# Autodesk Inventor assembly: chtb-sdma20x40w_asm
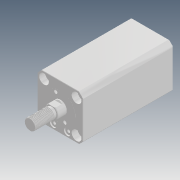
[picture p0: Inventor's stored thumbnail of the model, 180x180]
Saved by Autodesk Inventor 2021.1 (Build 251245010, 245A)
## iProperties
Company: Microsoft
Created: 2018-05
Part Number: chtb-sdma20x40w_asm
Description: STEP AP214
Document SubType Name: Assembly
Designer: user
Title: chtb-sdma20x40w_asm.STEP
Author: Windows
Revision Number: ÈÎºÎ
Sending System: SolidWorks 2015
Preprocessor: SwSTEP 2.0
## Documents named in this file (4)
- D:\Vault_2016\Projekty\Clamptek\Hydraulic\CHTB\CHTB-20\Inventor\CHTB-SDMA20x40W\chtb-sdma20x40w_asm.iam
- D:\Vault_2016\Projekty\Clamptek\Hydraulic\CHTB\CHTB-20\Inventor\CHTB-SDMA20x40W\CHTB-SDMA20X40NBT.ipt
- D:\Vault_2016\Projekty\Clamptek\Hydraulic\CHTB\CHTB-20\Inventor\CHTB-SDMA20x40W\CHTB-SDMA20X40WHSG.ipt
- D:\Vault_2016\Projekty\Clamptek\Hydraulic\CHTB\CHTB-20\Inventor\CHTB-SDMA20x40W\QG_3.ipt
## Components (3 placed, 3 different names)
1. CHTB-SDMA20X40NBT_1
2. CHTB-SDMA20X40WHSG_2
3. QG_3_3
